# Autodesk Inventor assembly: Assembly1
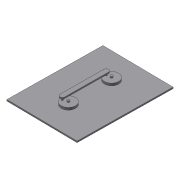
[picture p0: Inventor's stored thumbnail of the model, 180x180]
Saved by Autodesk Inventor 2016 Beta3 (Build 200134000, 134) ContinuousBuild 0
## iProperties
Created: 2016-03
Part Number: Assembly1
Document SubType Name: Assembly
Designer: Gaurav
Author: Gaurav
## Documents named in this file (4)
- D:\My Data\Books_Final Books\Autodesk Inventor 2015_resources\Chapter 7\Top-down\Assembly1.iam
- D:\My Data\Books_Final Books\Autodesk Inventor 2015_resources\Chapter 7\Top-down\Base.ipt
- D:\My Data\Books_Final Books\Autodesk Inventor 2015_resources\Chapter 7\Top-down\disc.ipt
- D:\My Data\Books_Final Books\Autodesk Inventor 2015_resources\Chapter 7\Top-down\Link.ipt
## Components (4 placed, 3 different names)
1. Base:1 — Mate:1, Mate:2, Mate:3, Mate:4, Mate:5
2. disc:1 — Mate:2, Mate:3, Flush:1
3. disc:2 — Mate:4, Mate:5
4. Link:1 — Flush:1
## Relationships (6: Mate 5, Flush 1)
- Mate:1: Base:1
- Mate:2: Base:1 ↔ disc:1
- Mate:3: Base:1 ↔ disc:1
- Mate:4: Base:1 ↔ disc:2
- Mate:5: Base:1 ↔ disc:2
- Flush:1: disc:1 ↔ Link:1
